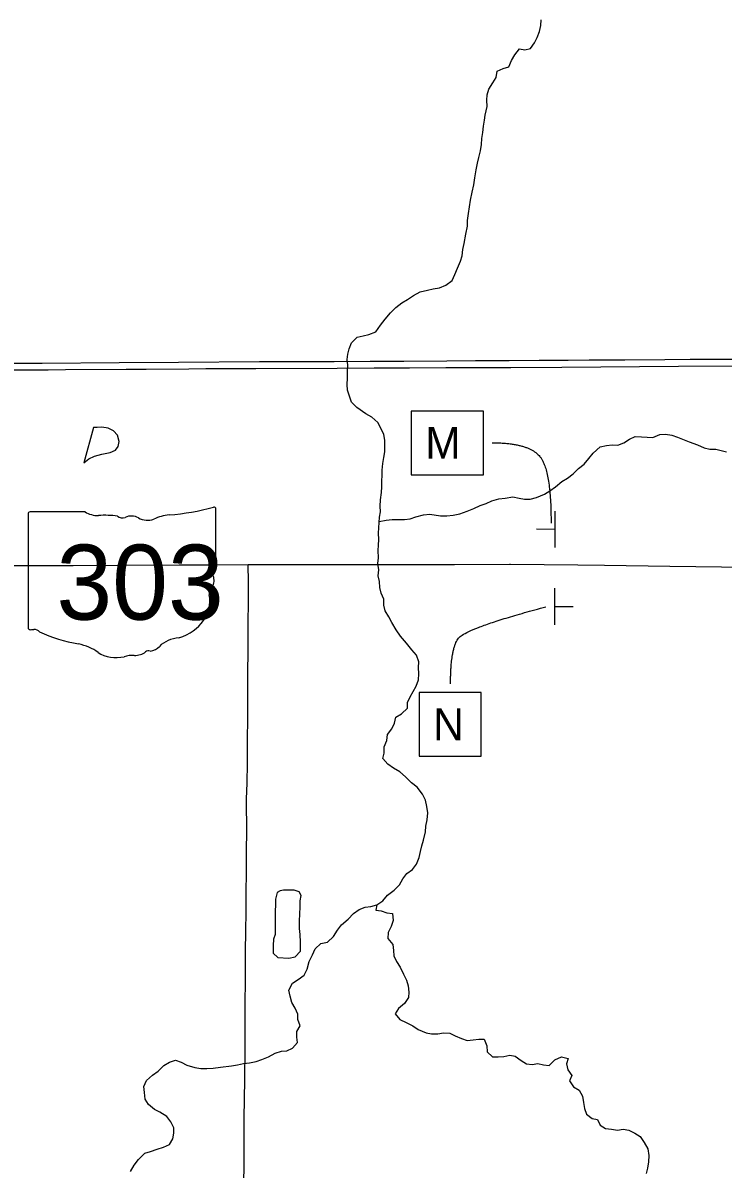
# Model space of a CAD drawing. Extents: x 0 to 34, y 0 to 22.
# Drawn here: x 7.55 to 10.62, y 14.41 to 19.45 of the extents above; entities that cross this region are included whole.
import ezdxf

# ---------------------------------------------------------------- set-up
doc = ezdxf.new("R2010")
doc.units = 0
for name, color, linetype in [('GM_X_Interstate_Route', 7, 'Continuous'), ('GM_X_Minor_Lake', 7, 'Continuous'), ('GM_X_Minor_River', 7, 'Continuous'), ('GM_X_State_Location', 7, 'Continuous'), ('GM_X_State_Route', 7, 'Continuous'), ('GM_X_State_Shield', 7, 'Continuous'), ('GM_X_Township_Road', 7, 'Continuous'), ('SH_Text', 7, 'Continuous'), ('SN_P_Signs', 7, 'Continuous')]:
    doc.layers.add(name, color=color, linetype=linetype)

msp = doc.modelspace()

# ---------------------------------------------------------------- linework, layer by layer
at = {"layer": 'GM_X_Interstate_Route'}
for points in [[(7.4719, 17.9218), (7.5489, 17.9221), (7.6598, 17.9224), (7.7361, 17.9227), (8.0027, 17.9242), (8.0905, 17.9246), (8.2781, 17.9264), (8.3517, 17.9271), (8.5716, 17.9273), (8.9286, 17.9295), (9.0917, 17.9306), (9.2471, 17.9311), (9.406, 17.9317), (9.5726, 17.9321), (9.6848, 17.9327), (9.6918, 17.9328), (9.9166, 17.9339), (10.4286, 17.9381), (10.7084, 17.9392), (10.9328, 17.9387), (10.9349, 17.9388), (11.0299, 17.9393)], [(7.4855, 17.9508), (7.6331, 17.951), (7.9707, 17.9537), (8.2319, 17.9553), (8.5873, 17.9579), (8.6762, 17.9582), (8.8556, 17.9588), (8.9164, 17.9591), (9.0735, 17.9597), (9.2222, 17.9604), (9.4117, 17.9613), (9.5373, 17.9623), (9.6657, 17.9628), (9.6847, 17.963), (9.8171, 17.9639), (9.9434, 17.9646), (10.0368, 17.9652), (10.0941, 17.9656), (10.1938, 17.9663), (10.3694, 17.9676), (10.4796, 17.9683), (10.6702, 17.9694)]]:
    msp.add_lwpolyline(points, dxfattribs=at)
at = {"layer": 'GM_X_Minor_Lake'}
for p, q in [((7.8593, 17.6687), (7.8165, 17.5134)), ((8.6565, 15.5466), (8.6567, 15.4403))]:
    msp.add_line(p, q, dxfattribs=at)
for points in [[(7.8165, 17.5134), (7.8381, 17.5307), (7.8626, 17.5424), (7.8947, 17.5513), (7.9316, 17.5584), (7.9551, 17.5682), (7.9673, 17.5845), (7.9717, 17.6073), (7.9648, 17.6348), (7.9466, 17.6545), (7.9228, 17.6656), (7.8953, 17.67), (7.8745, 17.6679), (7.8593, 17.6687)], [(8.6567, 15.4403), (8.6494, 15.4203), (8.6487, 15.3918), (8.6482, 15.3585), (8.6683, 15.3388), (8.7175, 15.3366), (8.7449, 15.3426), (8.7674, 15.3675), (8.7679, 15.4065), (8.7666, 15.4397), (8.7644, 15.4662), (8.764, 15.5004), (8.7646, 15.5289), (8.7662, 15.5612), (8.7668, 15.5878), (8.7713, 15.6116), (8.7616, 15.6276), (8.7407, 15.635), (8.6934, 15.6344), (8.6783, 15.6314), (8.666, 15.6246), (8.6588, 15.596), (8.6582, 15.5666), (8.6565, 15.5466)]]:
    msp.add_lwpolyline(points, dxfattribs=at)
at = {"layer": 'GM_X_Minor_River'}
for points in [[(9.5798, 19.0411), (9.5879, 19.0798), (9.5868, 19.1064), (9.5876, 19.1302), (9.5961, 19.1559), (9.613, 19.1826), (9.6281, 19.2074), (9.6318, 19.234), (9.6583, 19.2465), (9.6839, 19.2542), (9.6951, 19.2818), (9.7102, 19.3066), (9.73, 19.3324), (9.7537, 19.3278), (9.7793, 19.3336), (9.7963, 19.3584), (9.8085, 19.3832), (9.8188, 19.4089), (9.8244, 19.4346), (9.8262, 19.4602)], [(9.2502, 16.484), (9.2762, 16.5318), (9.2872, 16.5595), (9.2879, 16.5851), (9.2866, 16.6136), (9.2873, 16.6383), (9.2784, 16.6676), (9.2573, 16.692), (9.2333, 16.7212), (9.2074, 16.7513), (9.1891, 16.7795), (9.1689, 16.8116), (9.1563, 16.8361), (9.1399, 16.8634), (9.1349, 16.8881), (9.1337, 16.9137), (9.122, 16.9401), (9.1161, 16.9647), (9.1158, 16.9913), (9.1098, 17.0169), (9.1124, 17.0425), (9.1073, 17.071), (9.1108, 17.0957), (9.1095, 17.128), (9.1102, 17.1517), (9.1118, 17.1755), (9.1106, 17.2039), (9.1122, 17.2277), (9.1145, 17.2742), (9.1199, 17.298), (9.1187, 17.3227), (9.1203, 17.3512), (9.1237, 17.3826), (9.1254, 17.4082), (9.126, 17.4339), (9.1267, 17.4576), (9.1264, 17.4813), (9.1299, 17.5108), (9.1343, 17.5365), (9.1388, 17.5612), (9.1382, 17.6125), (9.1342, 17.6371), (9.1215, 17.6655), (9.108, 17.6909), (9.0822, 17.7134), (9.0546, 17.7283), (9.0154, 17.7563), (8.9915, 17.7798), (8.9827, 17.8062), (8.9748, 17.8327), (8.9726, 17.8574), (8.9742, 17.8859), (8.9739, 17.9134), (8.9765, 17.9419), (8.9733, 17.9666), (8.9759, 17.9903), (8.9823, 18.0142), (8.9924, 18.0399), (9.0167, 18.0649), (9.0432, 18.0709), (9.0687, 18.0778), (9.0989, 18.0896), (9.1203, 18.1183), (9.1408, 18.1451), (9.1642, 18.172), (9.1876, 18.196), (9.213, 18.2163), (9.2384, 18.2317), (9.2647, 18.2492), (9.2939, 18.2647), (9.326, 18.2727), (9.3505, 18.2777), (9.3789, 18.2828), (9.4072, 18.2945), (9.4344, 18.3148), (9.4464, 18.3406), (9.4584, 18.3682), (9.4704, 18.3988), (9.4786, 18.4235), (9.4812, 18.4511), (9.4866, 18.4768), (9.4946, 18.5177), (9.5018, 18.5529), (9.5025, 18.5786), (9.5059, 18.609), (9.5113, 18.6385), (9.5157, 18.667), (9.5229, 18.7022), (9.5291, 18.7355), (9.5345, 18.766), (9.5398, 18.8012), (9.5461, 18.8297), (9.5515, 18.8545), (9.5588, 18.884), (9.5632, 18.9125), (9.5648, 18.9382), (9.5692, 18.9648), (9.5727, 18.9934), (9.5771, 19.019), (9.5798, 19.0411)], [(9.1136, 17.2557), (9.144, 17.2613), (9.1715, 17.2635), (9.2245, 17.2641), (9.25, 17.2673), (9.2755, 17.2752), (9.3085, 17.2841), (9.336, 17.2873), (9.3834, 17.2803), (9.4108, 17.2796), (9.4392, 17.2828), (9.4685, 17.2889), (9.5006, 17.3006), (9.5298, 17.3124), (9.5581, 17.3251), (9.5835, 17.3339), (9.609, 17.3456), (9.6401, 17.3545), (9.6666, 17.3586), (9.7016, 17.3638), (9.7291, 17.3584), (9.7528, 17.354), (9.7774, 17.3533), (9.8048, 17.3603), (9.8397, 17.3759), (9.8641, 17.3895), (9.8886, 17.4078), (9.9158, 17.4309), (9.9412, 17.4464), (9.9665, 17.4647), (9.9899, 17.4888), (10.0143, 17.5071), (10.0349, 17.532), (10.0545, 17.556), (10.0845, 17.5829), (10.1119, 17.5899), (10.1374, 17.5921), (10.163, 17.5915), (10.1894, 17.6013), (10.2139, 17.6168), (10.2383, 17.6294), (10.2658, 17.6278), (10.2905, 17.6253), (10.316, 17.6246), (10.3472, 17.6373), (10.3718, 17.6386), (10.4002, 17.6342), (10.424, 17.6259), (10.4763, 17.6056), (10.5124, 17.5918), (10.541, 17.5798), (10.5666, 17.5725), (10.5922, 17.5738), (10.6396, 17.5611)], [(8.1926, 14.5177), (8.2065, 14.5416), (8.2119, 14.5664), (8.2117, 14.5901), (8.1981, 14.6165), (8.1808, 14.641), (8.1503, 14.6596), (8.1265, 14.6708), (8.0998, 14.6923), (8.0853, 14.7168), (8.0821, 14.7452), (8.0799, 14.7727), (8.0919, 14.7985), (8.1182, 14.8226), (8.1426, 14.839), (8.1679, 14.864), (8.1924, 14.8785), (8.2188, 14.8883), (8.2444, 14.8791), (8.2692, 14.8652), (8.3044, 14.8551), (8.33, 14.8516), (8.3565, 14.8519), (8.3849, 14.8532), (8.4161, 14.8564), (8.4652, 14.8627), (8.4917, 14.8678), (8.5172, 14.8728), (8.5446, 14.876), (8.573, 14.882), (8.5984, 14.8909), (8.6277, 14.9026), (8.6568, 14.9181), (8.6842, 14.927), (8.7088, 14.9292), (8.7333, 14.9399), (8.7548, 14.9658), (8.7517, 14.9895), (8.7524, 15.0133), (8.7672, 15.0391), (8.7565, 15.0665), (8.7562, 15.0902), (8.7446, 15.1166), (8.7301, 15.1412), (8.7232, 15.1696), (8.7172, 15.1961), (8.733, 15.2257), (8.7574, 15.2431), (8.7837, 15.2614), (8.7976, 15.2882), (8.8058, 15.3215), (8.8206, 15.3511), (8.8326, 15.3769), (8.8579, 15.3999), (8.8872, 15.406), (8.9134, 15.4319), (8.9302, 15.4587), (8.9488, 15.4827), (8.977, 15.5077), (9.0013, 15.5326), (9.0257, 15.55), (9.0521, 15.5608), (9.0777, 15.5639), (9.1031, 15.5709), (9.1295, 15.5883), (9.151, 15.6132), (9.1791, 15.6344), (9.2035, 15.6585), (9.2184, 15.6843), (9.2351, 15.7082), (9.2596, 15.7256), (9.2782, 15.7495), (9.2902, 15.7782), (9.2947, 15.8048), (9.301, 15.8305), (9.3083, 15.8543), (9.3174, 15.8915), (9.319, 15.9162), (9.3244, 15.9447), (9.3278, 15.9742), (9.3237, 16.0026), (9.3168, 16.0301), (9.3042, 16.0575), (9.2802, 16.0875), (9.2553, 16.1072), (9.2295, 16.1335), (9.2046, 16.155), (9.176, 16.1718), (9.1512, 16.1885), (9.1301, 16.2139), (9.1355, 16.2377), (9.1362, 16.2643), (9.1472, 16.2929), (9.1507, 16.3186), (9.1694, 16.3445), (9.1804, 16.3693), (9.1877, 16.3959), (9.2122, 16.4105), (9.2375, 16.4345), (9.2382, 16.4592), (9.2502, 16.484)], [(9.1031, 15.5709), (9.0987, 15.5471), (9.1224, 15.5445), (9.1471, 15.5353), (9.1727, 15.5318), (9.1759, 15.5024), (9.1667, 15.4757), (9.1528, 15.449), (9.1521, 15.4224), (9.1742, 15.3961), (9.1773, 15.3705), (9.1776, 15.3468), (9.1902, 15.3222), (9.2066, 15.2968), (9.2211, 15.2656), (9.2337, 15.2401), (9.2416, 15.2146), (9.2447, 15.1871), (9.2431, 15.1634), (9.2254, 15.1366), (9.1982, 15.1154), (9.1842, 15.0915), (9.2044, 15.067), (9.232, 15.0531), (9.2615, 15.0383), (9.2854, 15.0224), (9.3196, 15.0086), (9.3433, 15.0041), (9.3717, 15.0035), (9.3963, 15.0076), (9.4238, 15.006), (9.4476, 14.9949), (9.4752, 14.9829), (9.5008, 14.9737), (9.5264, 14.9768), (9.551, 14.98), (9.5756, 14.9803), (9.5873, 14.951), (9.5876, 14.9244), (9.6115, 14.9019), (9.6361, 14.9022), (9.6616, 14.9034), (9.6872, 14.9094), (9.7109, 14.905), (9.7376, 14.8863), (9.7614, 14.8714), (9.7861, 14.8688), (9.8107, 14.8729), (9.8363, 14.8675), (9.8609, 14.865), (9.8853, 14.89), (9.9154, 14.9027), (9.9439, 14.8954), (9.9366, 14.8716), (9.9426, 14.8451), (9.9608, 14.8206), (9.9497, 14.7967), (9.968, 14.7704), (9.9919, 14.7555), (10.0064, 14.7291), (10.0114, 14.7016), (10.0164, 14.676), (10.0252, 14.6505), (10.0491, 14.6318), (10.0728, 14.6273), (10.0845, 14.6018), (10.1083, 14.5869), (10.1339, 14.5844), (10.1605, 14.5809), (10.186, 14.584), (10.2107, 14.5796), (10.2373, 14.5666), (10.2611, 14.5517), (10.2775, 14.5253), (10.2939, 14.498), (10.299, 14.4695), (10.2974, 14.441), (10.292, 14.4134), (10.2866, 14.3897)], [(8.0206, 14.398), (8.0374, 14.4267), (8.056, 14.4506), (8.0841, 14.4785), (8.1096, 14.4864), (8.1379, 14.4962), (8.1662, 14.5051), (8.1926, 14.5177)]]:
    msp.add_lwpolyline(points, dxfattribs=at)
at = {"layer": 'GM_X_State_Route'}
msp.add_lwpolyline([(7.5027, 17.0624), (7.7699, 17.0625), (7.9858, 17.0635), (8.2343, 17.0648), (8.3692, 17.0653), (8.5376, 17.0658), (8.9084, 17.0667), (9.4445, 17.0669), (9.6858, 17.0677), (9.6903, 17.0677), (9.9868, 17.0643), (10.1033, 17.0627), (10.3908, 17.0589), (10.7326, 17.0543)], dxfattribs=at)
at = {"layer": 'GM_X_State_Shield'}
for p, q in [((7.5719, 17.289), (7.5719, 16.7887)), ((7.8214, 17.2976), (7.5801, 17.2976)), ((8.3959, 17.0482), (8.3959, 17.31)), ((8.3958, 17.0483), (8.3959, 17.0482))]:
    msp.add_line(p, q, dxfattribs=at)
for centre, major_axis, start_param, end_param in [((7.5814, 17.29), (0.00955, 0), 1.712693, 3.28349), ((7.8788, 17.3556), (0.0926, 0), 4.042523, 4.731795), ((7.9095, 17.0167), (0.3324, 0), 1.404758, 1.657858), ((7.985, 17.2926), (0.0267, 0), 3.836095, 5.185415), ((8.0242, 17.2348), (0.0555, 0), 0.950623, 2.079405), ((8.2138, 17.1448), (0.1758, 0), 1.699011, 2.107814), ((8.1024, 17.9796), (0.8738, 0), 4.814394, 5.042369), ((8.3868, 17.311), (0.00917, 0), 6.141152, 7.989035), ((8.0959, 17.3141), (0.0668, 0), 4.081561, 5.145723), ((8.3938, 17.029), (0.0142, 0), 1.883978, 3.671073), ((8.3861, 17.0472), (0.00982, 0), 5.05454, 6.418171), ((8.3035, 16.9959), (0.0852, 0), 5.934695, 6.695948), ((8.1513, 16.9054), (0.2186, 0), 5.101752, 6.440018), ((8.4288, 16.9387), (0.062, 0), 2.387724, 3.262537), ((7.5815, 16.7876), (0.00963, 0), 3.00124, 4.508301), ((7.5829, 16.8387), (0.0735, 0), 4.665946, 4.897461), ((7.598, 16.7598), (0.0265, 0), 0.519207, 1.627899), ((7.9325, 17.2093), (0.631, 0), 4.195997, 4.488961), ((8.2435, 16.6482), (0.1197, 0), 1.647645, 2.488434), ((7.7444, 16.5639), (0.1974, 0), 0.823519, 1.323587), ((7.9579, 16.7573), (0.1253, 0), 4.026481, 4.996735), ((8.0395, 16.7198), (0.0667, 0), 4.691044, 5.507374), ((8.0999, 16.6714), (0.0188, 0), 1.147584, 2.315152), ((8.0918, 16.7402), (0.0706, 0), 4.937069, 5.64225), ((8.0303, 16.5843), (0.1029, 0), 1.495662, 1.94098)]:
    msp.add_ellipse(centre, major_axis=major_axis, ratio=0.8, start_param=start_param, end_param=end_param, dxfattribs=at)
at = {"layer": 'GM_X_Township_Road'}
msp.add_lwpolyline([(8.5188, 14.3205), (8.5201, 14.4542), (8.5205, 14.5461), (8.5209, 14.6142), (8.5211, 14.6328), (8.5232, 14.8021), (8.524, 14.8438), (8.525, 14.8965), (8.5252, 14.9835), (8.5254, 15.0566), (8.5256, 15.1575), (8.5258, 15.2165), (8.5265, 15.3564), (8.528, 15.4636), (8.5282, 15.4837), (8.5287, 15.51), (8.5291, 15.5549), (8.5307, 15.7829), (8.5318, 15.9192), (8.5308, 16.0022), (8.5309, 16.0351), (8.5322, 16.0715), (8.5331, 16.106), (8.5353, 16.1939), (8.5373, 16.4915), (8.5369, 16.5288), (8.5367, 16.5645), (8.5385, 16.7121), (8.5388, 16.8115), (8.539, 16.9), (8.5391, 16.9886), (8.5376, 17.0658)], dxfattribs=at)
at = {"layer": 'SH_Text'}
for points in [[(9.2546, 17.4605), (9.5723, 17.4605), (9.5723, 17.7405), (9.2546, 17.7405)], [(9.2897, 16.2233), (9.5619, 16.2233), (9.5619, 16.5037), (9.2897, 16.5037)]]:
    msp.add_lwpolyline(points, close=True, dxfattribs=at)
for points in [[(9.61, 17.6014), (9.7694, 17.6014), (9.869, 17.4818), (9.869, 17.2487)], [(9.4274, 16.5415), (9.4274, 16.6976), (9.4972, 16.7874), (9.8458, 16.8804)]]:
    msp.add_open_spline(points, degree=2, dxfattribs=at)
at = {"layer": 'SN_P_Signs'}
for p, q in [((9.8862, 17.3005), (9.885, 17.1405)), ((9.8856, 17.2205), (9.8056, 17.2211)), ((9.8856, 16.8016), (9.8856, 16.9616)), ((9.8856, 16.8816), (9.9656, 16.8816))]:
    msp.add_line(p, q, dxfattribs=at)

# ---------------------------------------------------------------- texts
at = {"layer": 'GM_X_State_Location'}
for s, p in [('s', (7.9747, 17.0055)), ('r', (7.9746, 17.0055))]:
    msp.add_text(s, height=0.000473, dxfattribs=at).set_placement(p)
msp.add_text('303', height=0.000473, rotation=0, dxfattribs=at).set_placement((7.8075, 16.9711))
at = {"layer": 'GM_X_State_Shield'}
msp.add_text('303', height=0.32959, dxfattribs=at).set_placement((7.6956, 16.8239))
at = {"layer": 'SH_Text'}
for s, p in [('M', (9.3158, 17.5312)), ('N', (9.3508, 16.294))]:
    msp.add_text(s, height=0.14, dxfattribs=at).set_placement(p)

doc.saveas('drawing.dxf')
